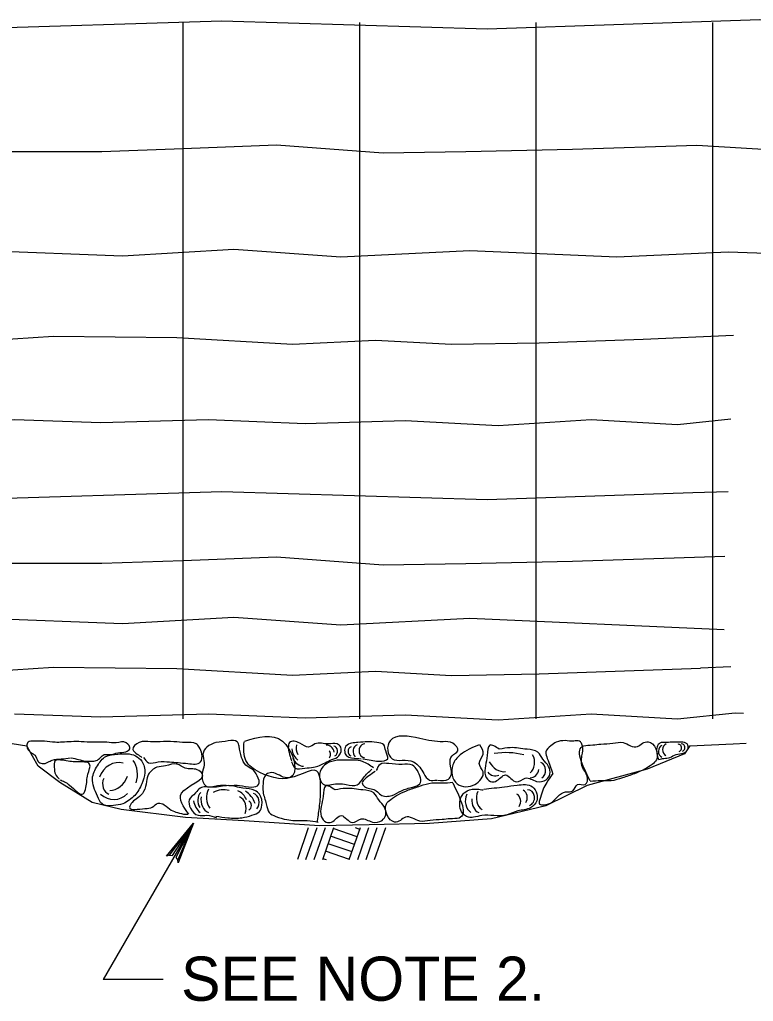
# Model space of a CAD drawing. Extents: x 13 to 918, y -903 to 879.
# Drawn here: x 173.6 to 225.6, y 543.9 to 613.4 of the extents above; entities that cross this region are included whole.
import ezdxf

# ---------------------------------------------------------------- set-up
doc = ezdxf.new("R2010")
doc.units = 0
for name, color, linetype in [('1', 7, 'Continuous'), ('2', 7, 'Continuous'), ('3', 7, 'Continuous')]:
    doc.layers.add(name, color=color, linetype=linetype)

msp = doc.modelspace()

# ---------------------------------------------------------------- linework, layer by layer
at = {"layer": '1'}
for p, q in [((223.78975, 596.94225), (232.98125, 596.60275)), ((194.071, 556.161), (193.298, 553.934)), ((194.66675, 556.161), (193.87925, 553.89225)), ((195.2625, 556.161), (194.475, 553.89225)), ((195.8585, 556.161), (195.071, 553.89225)), ((197.5355, 555.5195), (195.83975, 556.107)), ((197.73975, 556.161), (196.95425, 553.89225)), ((197.71875, 556.05075), (197.40425, 556.161)), ((198.3355, 556.161), (197.55, 553.89225)), ((198.92925, 556.161), (198.146, 553.89225)), ((199.52725, 556.161), (198.74175, 553.89225)), ((197.35225, 554.98825), (195.65625, 555.57775)), ((197.16875, 554.457), (195.471, 555.04225)), ((195.35, 553.89225), (195.10225, 553.97975)), ((196.9835, 553.92575), (195.2855, 554.511))]:
    msp.add_line(p, q, dxfattribs=at)
at = {"layer": '2'}
for p, q in [((185.19175, 613.19225), (185.19175, 563.89225)), ((197.69175, 613.19225), (197.69175, 563.89225)), ((210.19175, 613.19225), (210.19175, 563.89225)), ((222.69175, 613.19225), (222.69175, 569.21325)), ((222.69175, 569.21325), (222.69175, 563.89225)), ((185.95, 556.507), (179.55225, 545.4235)), ((183.80425, 545.4235), (179.55225, 545.4235))]:
    msp.add_line(p, q, dxfattribs=at)
for points in [[(97.69175, 613.009), (99.25425, 613.009), (104.871, 613.0965), (110.2605, 613.19225), (115.65225, 612.732), (126.71875, 613.19225), (142.046, 612.82775), (159.15625, 613.19225), (169.648, 612.732), (187.948, 613.28825), (206.725, 612.732), (226.04175, 613.384), (243.97725, 612.636), (249.25425, 613.009)], [(97.69175, 604.15475), (99.25425, 604.15475), (105.121, 604.15475), (111.14375, 604.32575), (116.62925, 603.86525), (123.6125, 604.25075), (129.65425, 603.961), (135.67725, 604.25075), (142.46675, 603.86525), (151.4835, 604.4215), (157.621, 603.961), (165.04375, 604.32575), (171.27725, 604.057), (179.45, 604.057), (185.223, 604.25075), (191.821, 604.51725), (199.37925, 603.94225), (205.22925, 604.03825), (212.76875, 604.211), (221.59175, 604.4985), (230.60625, 603.94225), (237.30225, 604.40275), (242.9605, 604.03825), (249.25425, 604.15475)], [(97.69175, 596.8735), (99.25425, 596.8735), (104.046, 596.5695), (108.975, 596.95275), (114.73125, 597.0485), (119.92925, 596.761), (126.06675, 597.0485), (132.396, 596.66525), (139.45625, 597.0485), (146.70625, 596.66525), (154.5125, 597.0485), (162.58975, 596.66525), (171.14375, 597.0485), (180.9085, 596.66525), (188.79175, 597.12575), (196.3875, 596.58825), (205.498, 597.0485), (215.91475, 596.58825), (223.78975, 596.94225)], [(97.69175, 590.6235), (99.25425, 590.6235), (104.2, 590.80075), (110.60625, 590.51325), (117.85625, 590.87775), (124.3605, 590.51325), (130.30625, 590.80075), (136.07925, 590.80075), (141.92925, 590.3215), (148.24175, 590.609), (154.475, 590.87775), (160.325, 590.3215), (167.3835, 590.41725), (176.0355, 590.9735), (184.7625, 590.87775), (192.95425, 590.41725), (198.823, 590.686), (204.2125, 590.3985), (210.42725, 590.4945), (217.775, 590.76325), (224.16475, 591.034)], [(97.69175, 584.8945), (99.25425, 584.8945), (101.4, 584.80075), (105.6, 585.0695), (109.70425, 584.72575), (115.671, 585.0695), (121.98125, 584.72575), (128.2355, 585.0695), (133.375, 584.72575), (139.073, 585.0695), (143.33125, 584.72575), (149.1625, 585.0695), (154.91675, 584.72575), (161.573, 585.01325), (166.521, 584.80075), (173.273, 585.0695), (179.373, 584.859), (187.00625, 585.0695), (193.85425, 584.782), (200.9335, 584.99225), (207.5125, 584.6485), (214.09175, 585.0695), (220.2105, 584.72575), (223.998, 585.11525)], [(122.25225, 579.684), (126.71875, 579.8695), (142.046, 579.50475), (159.15625, 579.8695), (169.648, 579.409), (187.948, 579.96525), (206.725, 579.409), (221.2875, 579.901)], [(221.2875, 579.90075), (223.7875, 579.984)], [(115.3105, 574.8195), (116.62925, 574.709), (123.6125, 575.0945), (129.65425, 574.80475), (135.67725, 575.0945), (142.46675, 574.709), (151.4835, 575.26525), (157.621, 574.80475), (165.04375, 575.1695), (171.27725, 574.90075), (179.45, 574.90075), (185.223, 575.0945), (191.821, 575.361), (199.37925, 574.786), (205.22925, 574.882), (212.76875, 575.05475), (223.553, 575.407)], [(109.74175, 570.9235), (114.73125, 571.007), (119.92925, 570.7195), (126.06675, 571.007), (132.396, 570.6235), (139.45625, 571.007), (146.70625, 570.6235), (154.5125, 571.007), (162.58975, 570.6235), (171.14375, 571.007), (180.9085, 570.6235), (188.79175, 571.084), (196.3875, 570.5465), (205.498, 571.007), (223.526, 570.2105)], [(97.69175, 567.186), (99.25425, 567.186), (104.2, 567.36325), (110.60625, 567.07575), (117.85625, 567.44025), (124.3605, 567.07575), (130.30625, 567.36325), (136.07925, 567.36325), (141.92925, 566.884), (148.24175, 567.1715), (154.475, 567.44025), (160.325, 566.884), (167.3835, 566.97975), (176.0355, 567.536), (184.7625, 567.44025), (192.95425, 566.97975), (198.823, 567.2485), (204.2125, 566.961), (210.42725, 567.057), (221.83, 567.47325)], [(221.82925, 567.4965), (223.9835, 567.58825)], [(173.273, 564.236), (179.373, 564.02575), (187.00625, 564.236), (193.85425, 563.9485), (200.9335, 564.159), (207.5125, 563.81525), (214.09175, 564.236), (220.2105, 563.89225), (224.296, 564.31325), (224.88975, 564.27575)], [(171.31675, 562.41525), (174.13975, 561.97575)], [(174.9585, 560.52575), (174.55625, 561.2485), (174.13975, 561.97575)], [(221.08125, 561.97975), (220.71675, 561.40275), (218.075, 560.31525), (213.80625, 559.15075), (210.9, 557.7195), (207.0375, 556.80275), (202.646, 556.47775), (198.37925, 556.384), (194.85425, 556.307), (189.523, 556.65075), (185.37925, 556.8985), (180.83125, 557.4715), (178.77725, 557.96725), (176.475, 559.37975), (174.9585, 560.52575)], [(221.08125, 561.97975), (224.14375, 562.107), (225.076, 562.16125)]]:
    msp.add_lwpolyline(points, dxfattribs=at)
for centre, major_axis, ratio, start_param, end_param in [((193.92112, 562.00117), (0, -1.27835), 0.81000006, 4.91291461, 5.68546904), ((193.67354, 561.77958), (0, -0.58551), 0.81000006, 4.26675203, 5.49844979), ((195.39317, 561.36559), (0, -0.64999), 0.80999929, 1.8064868, 3.22705677), ((195.38374, 561.36529), (0, 0.3211), 0.81000012, 3.8302894, 5.59448857), ((195.84227, 561.5919), (0, 0.36726), 0.81000001, 3.52063754, 6.17387931), ((197.16248, 561.57171), (0, -0.33692), 0.81000003, 3.3858717, 5.97461968), ((197.64069, 561.57697), (0, -0.49358), 0.81, 3.42609388, 5.60576039), ((198.06089, 561.62262), (0, 0.48655), 0.81, 6.25964382, 9.4097803), ((219.20926, 561.58103), (0, -0.43124), 0.81, 3.42997791, 5.94912269), ((219.50288, 561.69561), (0, -0.43124), 0.81, 3.42997791, 5.94912269), ((220.29609, 561.82672), (0, 0.25482), 0.81, 3.31482172, 6.56416766), ((220.52727, 561.84547), (0, 0.25482), 0.81, 3.31482172, 6.56416766), ((180.6251, 558.95411), (0, -1.83085), 0.80999992, 2.90519842, 4.26729153), ((180.7478, 559.94086), (0, 1.51741), 0.81, 4.32037218, 5.41870346), ((193.76155, 561.63039), (0, -1.10495), 0.81, 5.19521851, 6.26103451), ((208.05914, 553.72139), (0, 7.76681), 0.81000001, 6.07827013, 6.41429769), ((209.36205, 560.78998), (0, 0.90904), 0.81000003, 3.75873187, 5.34263062), ((207.94477, 561.70771), (0, -1.56974), 0.8100001, 5.29149955, 6.35808359), ((209.75594, 560.5433), (0, 0.83936), 0.81000017, 3.18899735, 4.41400245), ((210.39535, 560.23323), (0, 0.58921), 0.81, 3.60011639, 5.96237459), ((180.12848, 559.27406), (0, -0.76561), 0.81000009, 4.17603296, 5.99374272), ((180.00814, 560.50415), (0, 1.6972), 0.81, 3.14579468, 4.29713608), ((207.31121, 560.82499), (0, -0.98017), 0.81000001, 5.53758972, 6.60279368), ((187.76153, 558.28496), (0, -1.10748), 0.81, 4.12057168, 5.44223554), ((188.06807, 556.64245), (0, 2.22065), 0.81000002, 6.05784231, 6.69927815), ((209.12236, 558.31426), (0, 0.55541), 0.81000001, 3.99878784, 5.89240594), ((209.64454, 558.29838), (0, -0.55062), 0.81000001, 0.18304674, 3.27017547), ((180.30294, 560.11916), (0, 1.94346), 0.81000001, 2.50269394, 3.81217884), ((186.87016, 558.08957), (0, -0.77287), 0.81000008, 3.85566653, 5.39025251), ((187.26049, 558.16055), (0, -0.9728), 0.81000001, 4.49814671, 5.94647978), ((188.75986, 557.51735), (0, 1.33372), 0.81000001, 5.2143354, 5.9749508), ((188.96903, 557.53229), (0, 0.86919), 0.81000008, 4.30016029, 5.93267335), ((188.97073, 557.11753), (0, 1.82437), 0.80999993, 5.14978376, 5.82128193), ((190.0901, 557.97709), (0, 0.63071), 0.81, 3.87620111, 6.0940258), ((205.92957, 558.07259), (0, -0.91741), 0.81000003, 4.18007151, 5.79785675), ((206.37171, 558.08286), (0, -0.88792), 0.81000005, 4.56268598, 5.95485431), ((206.71763, 558.26426), (0, -0.91741), 0.81000003, 4.18007151, 5.79785675), ((208.6583, 558.04551), (0, 0.55541), 0.81000001, 3.99878784, 5.89240594), ((187.2186, 558.57161), (0, -1.6602), 0.81000003, 5.01177777, 5.64076646), ((189.78529, 557.74863), (0, 0.32799), 0.81000006, 3.42851363, 5.99626438)]:
    msp.add_ellipse(centre, major_axis=major_axis, ratio=ratio, start_param=start_param, end_param=end_param, dxfattribs=at)
for points in [[(177.29175, 561.11725), (177.80425, 561.00275), (178.3125, 560.88825), (178.72925, 560.88825), (179.05625, 560.92575), (179.3625, 561.15475), (179.62725, 561.3465), (180.04375, 561.3465), (180.5855, 561.47975), (181.1585, 561.55475), (181.4355, 561.7465), (181.1875, 562.186), (180.47725, 562.186), (179.8125, 562.2235), (178.85625, 562.2235), (177.98975, 562.261), (177.29175, 562.261), (176.6605, 562.2235), (176.148, 562.2235), (175.40625, 562.30075), (174.67925, 562.30075), (174.23125, 562.2235), (174.13975, 561.97575), (174.55625, 561.4215), (174.7105, 561.307), (174.92725, 560.88825), (175.221, 560.71525), (175.6375, 560.811), (175.948, 560.96325), (176.56675, 561.04025), (177.23125, 561.11725)], [(182.4105, 561.15475), (182.76475, 560.7735), (183.446, 560.82975), (184.25, 560.82975), (185.548, 560.71525), (186.446, 560.82975), (186.5375, 561.384), (186.35225, 561.87975), (186.1335, 562.109), (185.3625, 562.20475), (184.5585, 562.261), (183.5835, 562.261), (182.90625, 562.261), (182.1, 562.20475), (181.65225, 561.709), (181.9625, 561.384), (182.2855, 561.15475)], [(187.5125, 562.20475), (186.89175, 561.87975), (186.61475, 561.384), (186.70625, 560.7735), (186.5835, 560.16325), (186.61475, 559.457), (186.846, 559.11325), (187.65, 559.1695), (188.45625, 559.1695), (189.2105, 559.1695), (190.0625, 559.05475), (190.55625, 559.22775), (190.4625, 559.83825), (190.0625, 560.334), (189.6585, 560.60075), (189.35225, 561.15475), (189.16675, 561.93825), (189.04175, 562.261), (188.4085, 562.3195), (187.55625, 562.20475)], [(189.56875, 562.2985), (192.24175, 562.2985), (192.96875, 559.87575), (190.6355, 560.086), (189.6605, 560.92575), (189.523, 562.24225)], [(192.89175, 560.82975), (193.15225, 560.39025), (193.81875, 560.39025), (194.45225, 560.4485), (195.25625, 560.7735), (195.75, 561.00275), (196.246, 561.2695), (196.36875, 561.87975), (196.10625, 562.109), (195.4875, 562.109), (194.546, 562.109), (194.096, 561.87975), (193.4625, 562.16525), (192.75, 562.20475), (192.6585, 561.8235), (192.798, 561.211), (192.89175, 560.88825)], [(203.21675, 559.55075), (203.98975, 559.609), (204.20625, 559.95275), (204.11475, 560.71525), (204.25425, 561.2695), (204.65625, 561.61325), (204.3, 562.16525), (203.61875, 562.261), (201.96475, 562.49025), (199.8625, 562.3195), (199.69375, 561.65075), (200.00225, 561.059), (200.7125, 560.9445), (201.51875, 560.82975), (201.96475, 560.4485), (202.24375, 560.009), (202.646, 559.55075), (203.173, 559.55075)], [(211.37925, 560.009), (210.9625, 559.37975), (210.7, 558.90275), (210.51475, 558.311), (210.45225, 557.834), (210.73125, 557.7965), (211.36475, 558.00475), (211.75, 558.38825), (212.29175, 558.711), (212.80225, 558.78825), (213.12725, 559.22775), (213.66875, 559.22775), (213.823, 559.8195), (213.4835, 560.4485), (213.41875, 561.04025), (213.4835, 561.459), (213.45, 562.09025), (213.28125, 562.30075), (212.86475, 562.30075), (212.2605, 562.33825), (211.62925, 562.2235), (211.23975, 561.97575), (210.9, 561.536), (210.99375, 561.07775), (211.2085, 560.52575), (211.36475, 560.009)], [(197.94375, 561.059), (198.51675, 560.9445), (199.0585, 560.88825), (199.69375, 561.059), (199.55425, 561.61325), (199.41475, 562.05075), (198.921, 562.20475), (198.25625, 562.261), (197.58975, 562.20475), (197.14175, 562.16525), (196.74175, 561.93825), (196.648, 561.55475), (196.7855, 561.2695), (197.14175, 561.11725), (197.8085, 561.059)], [(206.173, 562.05275), (204.82725, 561.32775), (204.3, 560.6215), (204.6085, 559.286), (205.22925, 559.07575), (205.8605, 559.22975), (206.45, 560.12575), (206.173, 560.71725), (206.45, 561.386), (206.21675, 562.05275)], [(207.59375, 561.72575), (208.36675, 561.84025), (209.56875, 561.72575), (210.32925, 561.51725), (210.6835, 561.0195), (211.0875, 560.50475), (211.17925, 559.9715), (210.91675, 559.5695), (210.2355, 559.45475), (209.4335, 559.684), (208.8125, 559.41725), (208.03975, 559.91325), (207.32925, 559.45475), (206.973, 559.45475), (206.61875, 559.857), (206.61875, 560.56325), (206.74175, 561.28825), (206.92725, 562.01325), (207.59375, 561.72575)], [(214.023, 559.4945), (213.575, 561.97575), (214.2085, 562.034), (214.78125, 562.09025), (215.62925, 562.1485), (216.35625, 562.20475), (216.88125, 561.97575), (217.37725, 561.9195), (217.7335, 562.1485), (218.1355, 562.26325), (218.721, 560.984), (218.4125, 560.659), (217.873, 560.31525), (217.1625, 559.99225), (216.3105, 559.70475), (215.5085, 559.4945), (214.78125, 559.4945), (214.023, 559.43825)], [(218.89175, 561.00275), (219.248, 561.07775), (219.66675, 561.15475), (220.11475, 561.3465), (220.623, 561.459), (220.95, 561.7465), (220.95, 562.01325), (220.8085, 562.16525), (220.33125, 562.2235), (219.821, 562.2235), (219.33975, 562.20475), (218.96875, 562.16525), (218.76875, 561.8985), (218.7375, 561.536), (218.83125, 561.07775), (218.8625, 561.00275)], [(176.48975, 559.5715), (177.16875, 559.19025), (178.14375, 558.57775), (178.33125, 559.01725), (178.46875, 559.95275), (178.59175, 560.67775), (177.69375, 560.82975), (176.675, 560.9445), (176.1355, 560.88825), (176.0875, 560.4485), (176.17925, 559.95275), (176.44375, 559.62775)], [(180.93975, 557.85475), (181.79175, 558.46525), (182.2855, 559.286), (182.50225, 560.06725), (182.2855, 560.88825), (181.8375, 561.2695), (180.5835, 561.384), (179.7355, 561.21325), (179.146, 560.56325), (178.78975, 559.66725), (179.146, 558.407), (179.471, 557.85475), (180.275, 557.74025), (180.93975, 557.85475)], [(198.69375, 560.407), (197.9085, 560.861), (196.675, 560.95275), (195.91875, 560.9195), (194.86675, 559.9715), (195.221, 559.211), (195.725, 559.23825), (196.7625, 559.232), (197.53975, 559.211), (197.9875, 559.707), (198.575, 560.3215)], [(185.625, 557.12775), (185.1, 558.61725), (186.56875, 560.011), (186.2125, 560.27775), (185.3625, 560.39225), (184.775, 560.67775), (183.971, 560.56325), (183.35425, 560.4485), (182.76475, 559.95275), (182.625, 559.457), (182.4105, 558.732), (182.0085, 558.29225), (181.60625, 557.9695), (181.421, 557.62575), (182.50225, 557.52975), (183.02725, 557.62575), (183.446, 557.911), (183.87925, 557.7965), (184.373, 557.41525), (184.821, 557.24225), (185.3625, 557.12775), (185.548, 557.12775)], [(194.71675, 556.536), (194.85425, 557.586), (194.946, 558.8445), (194.6835, 560.182), (192.44175, 559.7235), (191.3625, 560.06725), (191.05225, 559.8945), (190.86675, 559.284), (190.86675, 558.72975), (191.098, 557.85275), (191.3125, 557.24225), (191.7625, 556.97575), (192.56475, 556.7465), (193.10625, 556.68825), (194.00425, 556.68825), (194.7605, 556.5735)], [(198.796, 560.16325), (198.348, 559.83825), (197.9, 559.284), (198.11475, 559.05475), (198.8875, 558.78825), (199.198, 558.50275), (200.00225, 558.46325), (200.66675, 558.78825), (201.46875, 559.05475), (201.96475, 559.284), (201.79375, 560.2195), (201.43975, 560.60075), (200.7125, 560.659), (199.76875, 560.71525), (199.15225, 560.659), (198.8875, 560.2195)], [(187.52725, 556.9945), (188.37725, 556.87975), (189.36875, 556.87975), (190.07925, 557.05275), (190.61875, 557.3195), (190.7875, 557.759), (190.61875, 558.54025), (190.29375, 558.807), (189.44375, 558.97975), (188.425, 559.15075), (187.26475, 559.036), (186.41475, 558.97975), (186.09175, 558.636), (185.64175, 558.14025), (185.7355, 557.5485), (186.275, 557.05275), (186.89375, 557.05275), (187.575, 556.87975)], [(195.96875, 558.8445), (196.74175, 558.959), (197.94375, 558.8445), (198.70225, 558.636), (199.0585, 558.13825), (199.4625, 557.6235), (199.55425, 557.09025), (199.29175, 556.68825), (198.6105, 556.5735), (197.8085, 556.80275), (197.1875, 556.536), (196.41475, 557.032), (195.70425, 556.5735), (195.348, 556.5735), (194.99375, 556.97575), (194.99375, 557.682), (195.11675, 558.407), (195.30225, 559.132), (195.96875, 558.8445)], [(204.3, 559.34225), (204.748, 556.861), (204.11475, 556.80275), (203.54375, 556.7465), (202.69175, 556.68825), (201.96475, 556.632), (201.43975, 556.861), (200.946, 556.91725), (200.58975, 556.68825), (200.1875, 556.5735), (199.6, 557.85275), (199.9105, 558.17775), (200.45, 558.5215), (201.1625, 558.8445), (202.0125, 559.132), (202.81675, 559.34225), (203.54375, 559.34225), (204.3, 559.3985)], [(206.49375, 558.90275), (207.96475, 559.0735), (208.8605, 559.18825), (209.94175, 559.0735), (210.25, 558.57775), (210.25, 558.082), (209.80425, 557.586), (208.90625, 557.357), (208.15, 557.09025), (207.20625, 557.032), (206.35625, 557.032), (205.76875, 556.91725), (205.4125, 556.91725), (204.91875, 557.2985), (204.79375, 557.7965), (204.9625, 558.46325), (205.31875, 558.78825), (206.046, 558.90275), (206.448, 558.8445)]]:
    msp.add_spline(points, degree=3, dxfattribs=at)
at = {"layer": '3'}
msp.add_lwpolyline([(184.223, 554.22775), (184.45425, 554.21525), (185.95, 556.507), (184.223, 554.22775), (184.04175, 554.16325), (185.95, 556.507), (184.70225, 554.07575), (184.82925, 553.886), (185.95, 556.507), (184.86875, 553.686), (184.82925, 553.886)], dxfattribs=at)

# ---------------------------------------------------------------- texts
msp.add_text('SEE NOTE 2.', height=3.1249995, dxfattribs=at).set_placement((185.06875, 543.9235))

doc.saveas('drawing.dxf')
